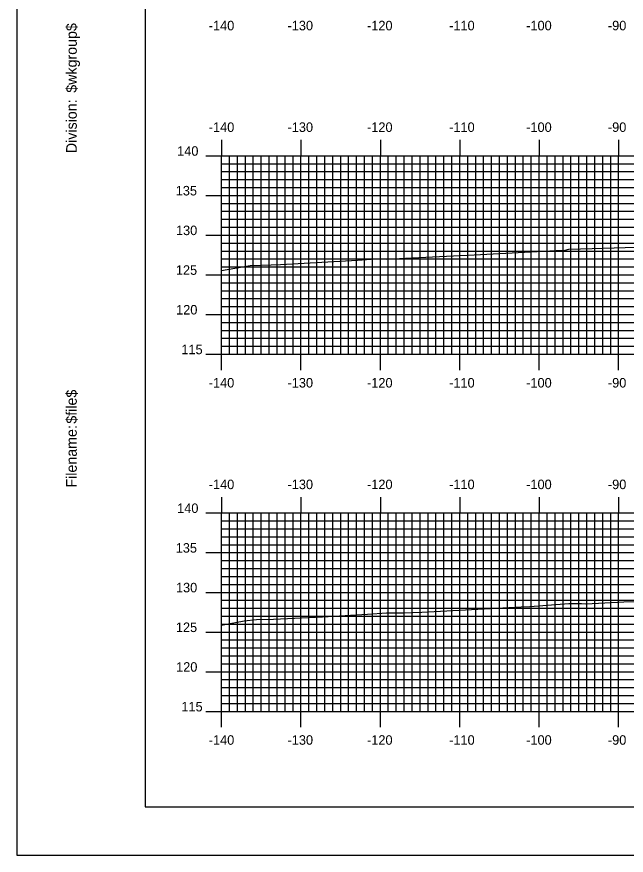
# Model space of a CAD drawing. Extents: x 841782 to 842125, y 363538 to 363758.
# Drawn here: x 841781.6 to 841858.3, y 363537.6 to 363643.2 of the extents above; entities that cross this region are included whole.
import ezdxf

# ---------------------------------------------------------------- set-up
doc = ezdxf.new("R2010")
doc.units = 0
for name, color, linetype in [('BORDER', 7, 'Continuous'), ('H_V ANNOTATION', 7, 'Continuous'), ('M_Roadway_Centerline', 7, 'Continuous'), ('MAJOR', 7, 'Continuous'), ('MINOR', 7, 'Continuous'), ('PLOT BOUNDARY', 7, 'Continuous'), ('S_Roadway_Centerline', 7, 'Continuous')]:
    doc.layers.add(name, color=color, linetype=linetype)

msp = doc.modelspace()

# ---------------------------------------------------------------- linework, layer by layer
at = {"layer": 'BORDER'}
msp.add_lwpolyline([(841797.77, 363543.72), (842117.77, 363543.72), (842117.77, 363753.72), (841797.77, 363753.72)], close=True, dxfattribs=at)
at = {"layer": 'MAJOR'}
for p, q in [((841807.37, 363627.73), (841807.37, 363625.72)), ((841817.37, 363627.73), (841817.37, 363625.72)), ((841827.37, 363627.73), (841827.37, 363625.72)), ((841837.37, 363627.73), (841837.37, 363625.72)), ((841847.37, 363627.73), (841847.37, 363625.72)), ((841857.37, 363627.73), (841857.37, 363625.72)), ((841805.37, 363625.72), (841807.37, 363625.72)), ((841807.37, 363625.72), (842087.37, 363625.72)), ((841807.37, 363600.72), (841807.37, 363625.72)), ((841807.37, 363600.72), (841807.37, 363625.72)), ((841807.37, 363625.72), (842087.37, 363625.72)), ((841817.37, 363600.72), (841817.37, 363625.72)), ((841827.37, 363600.72), (841827.37, 363625.72)), ((841837.37, 363600.72), (841837.37, 363625.72)), ((841847.37, 363600.72), (841847.37, 363625.72)), ((841857.37, 363600.72), (841857.37, 363625.72)), ((841805.37, 363620.72), (841807.37, 363620.72)), ((841807.37, 363620.72), (842087.37, 363620.72)), ((841805.37, 363615.72), (841807.37, 363615.72)), ((841807.37, 363615.72), (842087.37, 363615.72)), ((841805.37, 363610.72), (841807.37, 363610.72)), ((841807.37, 363610.72), (842087.37, 363610.72)), ((841805.37, 363605.72), (841807.37, 363605.72)), ((841807.37, 363605.72), (842087.37, 363605.72)), ((841805.37, 363600.72), (841807.37, 363600.72)), ((841807.37, 363600.72), (842087.37, 363600.72)), ((841807.37, 363600.72), (842087.37, 363600.72)), ((841807.37, 363598.72), (841807.37, 363600.72)), ((841817.37, 363598.72), (841817.37, 363600.72)), ((841827.37, 363598.72), (841827.37, 363600.72)), ((841837.37, 363598.72), (841837.37, 363600.72)), ((841847.37, 363598.72), (841847.37, 363600.72)), ((841857.37, 363598.72), (841857.37, 363600.72)), ((841807.37, 363582.73), (841807.37, 363580.72)), ((841817.37, 363582.73), (841817.37, 363580.72)), ((841827.37, 363582.73), (841827.37, 363580.72)), ((841837.37, 363582.73), (841837.37, 363580.72)), ((841847.37, 363582.73), (841847.37, 363580.72)), ((841857.37, 363582.73), (841857.37, 363580.72)), ((841805.37, 363580.72), (841807.37, 363580.72)), ((841807.37, 363580.72), (842087.37, 363580.72)), ((841807.37, 363555.72), (841807.37, 363580.72)), ((841807.37, 363555.72), (841807.37, 363580.72)), ((841807.37, 363580.72), (842087.37, 363580.72)), ((841817.37, 363555.72), (841817.37, 363580.72)), ((841827.37, 363555.72), (841827.37, 363580.72)), ((841837.37, 363555.72), (841837.37, 363580.72)), ((841847.37, 363555.72), (841847.37, 363580.72)), ((841857.37, 363555.72), (841857.37, 363580.72)), ((841805.37, 363575.72), (841807.37, 363575.72)), ((841807.37, 363575.72), (842087.37, 363575.72)), ((841805.37, 363570.72), (841807.37, 363570.72)), ((841807.37, 363570.72), (842087.37, 363570.72)), ((841805.37, 363565.72), (841807.37, 363565.72)), ((841807.37, 363565.72), (842087.37, 363565.72)), ((841805.37, 363560.72), (841807.37, 363560.72)), ((841807.37, 363560.72), (842087.37, 363560.72)), ((841805.37, 363555.72), (841807.37, 363555.72)), ((841807.37, 363555.72), (842087.37, 363555.72)), ((841807.37, 363555.72), (842087.37, 363555.72)), ((841807.37, 363553.72), (841807.37, 363555.72)), ((841817.37, 363553.72), (841817.37, 363555.72)), ((841827.37, 363553.72), (841827.37, 363555.72)), ((841837.37, 363553.72), (841837.37, 363555.72)), ((841847.37, 363553.72), (841847.37, 363555.72)), ((841857.37, 363553.72), (841857.37, 363555.72))]:
    msp.add_line(p, q, dxfattribs=at)
at = {"layer": 'MINOR'}
for p, q in [((841808.37, 363600.72), (841808.37, 363625.72)), ((841809.37, 363600.72), (841809.37, 363625.72)), ((841810.37, 363600.72), (841810.37, 363625.72)), ((841811.37, 363600.72), (841811.37, 363625.72)), ((841812.37, 363600.72), (841812.37, 363625.72)), ((841813.37, 363600.72), (841813.37, 363625.72)), ((841814.37, 363600.72), (841814.37, 363625.72)), ((841815.37, 363600.72), (841815.37, 363625.72)), ((841816.37, 363600.72), (841816.37, 363625.72)), ((841818.37, 363600.72), (841818.37, 363625.72)), ((841819.37, 363600.72), (841819.37, 363625.72)), ((841820.37, 363600.72), (841820.37, 363625.72)), ((841821.37, 363600.72), (841821.37, 363625.72)), ((841822.37, 363600.72), (841822.37, 363625.72)), ((841823.37, 363600.72), (841823.37, 363625.72)), ((841824.37, 363600.72), (841824.37, 363625.72)), ((841825.37, 363600.72), (841825.37, 363625.72)), ((841826.37, 363600.72), (841826.37, 363625.72)), ((841828.37, 363600.72), (841828.37, 363625.72)), ((841829.37, 363600.72), (841829.37, 363625.72)), ((841830.37, 363600.72), (841830.37, 363625.72)), ((841831.37, 363600.72), (841831.37, 363625.72)), ((841832.37, 363600.72), (841832.37, 363625.72)), ((841833.37, 363600.72), (841833.37, 363625.72)), ((841834.37, 363600.72), (841834.37, 363625.72)), ((841835.37, 363600.72), (841835.37, 363625.72)), ((841836.37, 363600.72), (841836.37, 363625.72)), ((841838.37, 363600.72), (841838.37, 363625.72)), ((841839.37, 363600.72), (841839.37, 363625.72)), ((841840.37, 363600.72), (841840.37, 363625.72)), ((841841.37, 363600.72), (841841.37, 363625.72)), ((841842.37, 363600.72), (841842.37, 363625.72)), ((841843.37, 363600.72), (841843.37, 363625.72)), ((841844.37, 363600.72), (841844.37, 363625.72)), ((841845.37, 363600.72), (841845.37, 363625.72)), ((841846.37, 363600.72), (841846.37, 363625.72)), ((841848.37, 363600.72), (841848.37, 363625.72)), ((841849.37, 363600.72), (841849.37, 363625.72)), ((841850.37, 363600.72), (841850.37, 363625.72)), ((841851.37, 363600.72), (841851.37, 363625.72)), ((841852.37, 363600.72), (841852.37, 363625.72)), ((841853.37, 363600.72), (841853.37, 363625.72)), ((841854.37, 363600.72), (841854.37, 363625.72)), ((841855.37, 363600.72), (841855.37, 363625.72)), ((841856.37, 363600.72), (841856.37, 363625.72)), ((841807.37, 363624.72), (842087.37, 363624.72)), ((841807.37, 363624.72), (841809.38, 363624.72)), ((841807.37, 363623.72), (842087.37, 363623.72)), ((841807.37, 363623.72), (841809.38, 363623.72)), ((841807.37, 363622.72), (842087.37, 363622.72)), ((841807.37, 363622.72), (841809.38, 363622.72)), ((841807.37, 363621.72), (842087.37, 363621.72)), ((841807.37, 363621.72), (841809.38, 363621.72)), ((841807.37, 363619.72), (842087.37, 363619.72)), ((841807.37, 363619.72), (841809.38, 363619.72)), ((841807.37, 363618.72), (842087.37, 363618.72)), ((841807.37, 363618.72), (841809.38, 363618.72)), ((841807.37, 363617.72), (842087.37, 363617.72)), ((841807.37, 363617.72), (841809.38, 363617.72)), ((841807.37, 363616.72), (842087.37, 363616.72)), ((841807.37, 363616.72), (841809.38, 363616.72)), ((841807.37, 363614.72), (842087.37, 363614.72)), ((841807.37, 363614.72), (841809.38, 363614.72)), ((841807.37, 363613.72), (842087.37, 363613.72)), ((841807.37, 363613.72), (841809.38, 363613.72)), ((841807.37, 363612.72), (842087.37, 363612.72)), ((841807.37, 363612.72), (841809.38, 363612.72)), ((841807.37, 363611.72), (842087.37, 363611.72)), ((841807.37, 363611.72), (841809.38, 363611.72)), ((841807.37, 363609.72), (842087.37, 363609.72)), ((841807.37, 363609.72), (841809.38, 363609.72)), ((841807.37, 363608.72), (842087.37, 363608.72)), ((841807.37, 363608.72), (841809.38, 363608.72)), ((841807.37, 363607.72), (842087.37, 363607.72)), ((841807.37, 363607.72), (841809.38, 363607.72)), ((841807.37, 363606.72), (842087.37, 363606.72)), ((841807.37, 363606.72), (841809.38, 363606.72)), ((841807.37, 363604.72), (842087.37, 363604.72)), ((841807.37, 363604.72), (841809.38, 363604.72)), ((841807.37, 363603.72), (842087.37, 363603.72)), ((841807.37, 363603.72), (841809.38, 363603.72)), ((841807.37, 363602.72), (842087.37, 363602.72)), ((841807.37, 363602.72), (841809.38, 363602.72)), ((841807.37, 363601.72), (842087.37, 363601.72)), ((841807.37, 363601.72), (841809.38, 363601.72)), ((841808.37, 363555.72), (841808.37, 363580.72)), ((841809.37, 363555.72), (841809.37, 363580.72)), ((841810.37, 363555.72), (841810.37, 363580.72)), ((841811.37, 363555.72), (841811.37, 363580.72)), ((841812.37, 363555.72), (841812.37, 363580.72)), ((841813.37, 363555.72), (841813.37, 363580.72)), ((841814.37, 363555.72), (841814.37, 363580.72)), ((841815.37, 363555.72), (841815.37, 363580.72)), ((841816.37, 363555.72), (841816.37, 363580.72)), ((841818.37, 363555.72), (841818.37, 363580.72)), ((841819.37, 363555.72), (841819.37, 363580.72)), ((841820.37, 363555.72), (841820.37, 363580.72)), ((841821.37, 363555.72), (841821.37, 363580.72)), ((841822.37, 363555.72), (841822.37, 363580.72)), ((841823.37, 363555.72), (841823.37, 363580.72)), ((841824.37, 363555.72), (841824.37, 363580.72)), ((841825.37, 363555.72), (841825.37, 363580.72)), ((841826.37, 363555.72), (841826.37, 363580.72)), ((841828.37, 363555.72), (841828.37, 363580.72)), ((841829.37, 363555.72), (841829.37, 363580.72)), ((841830.37, 363555.72), (841830.37, 363580.72)), ((841831.37, 363555.72), (841831.37, 363580.72)), ((841832.37, 363555.72), (841832.37, 363580.72)), ((841833.37, 363555.72), (841833.37, 363580.72)), ((841834.37, 363555.72), (841834.37, 363580.72)), ((841835.37, 363555.72), (841835.37, 363580.72)), ((841836.37, 363555.72), (841836.37, 363580.72)), ((841838.37, 363555.72), (841838.37, 363580.72)), ((841839.37, 363555.72), (841839.37, 363580.72)), ((841840.37, 363555.72), (841840.37, 363580.72)), ((841841.37, 363555.72), (841841.37, 363580.72)), ((841842.37, 363555.72), (841842.37, 363580.72)), ((841843.37, 363555.72), (841843.37, 363580.72)), ((841844.37, 363555.72), (841844.37, 363580.72)), ((841845.37, 363555.72), (841845.37, 363580.72)), ((841846.37, 363555.72), (841846.37, 363580.72)), ((841848.37, 363555.72), (841848.37, 363580.72)), ((841849.37, 363555.72), (841849.37, 363580.72)), ((841850.37, 363555.72), (841850.37, 363580.72)), ((841851.37, 363555.72), (841851.37, 363580.72)), ((841852.37, 363555.72), (841852.37, 363580.72)), ((841853.37, 363555.72), (841853.37, 363580.72)), ((841854.37, 363555.72), (841854.37, 363580.72)), ((841855.37, 363555.72), (841855.37, 363580.72)), ((841856.37, 363555.72), (841856.37, 363580.72)), ((841807.37, 363579.72), (842087.37, 363579.72)), ((841807.37, 363579.72), (841809.38, 363579.72)), ((841807.37, 363578.72), (842087.37, 363578.72)), ((841807.37, 363578.72), (841809.38, 363578.72)), ((841807.37, 363577.72), (842087.37, 363577.72)), ((841807.37, 363577.72), (841809.38, 363577.72)), ((841807.37, 363576.72), (842087.37, 363576.72)), ((841807.37, 363576.72), (841809.38, 363576.72)), ((841807.37, 363574.72), (842087.37, 363574.72)), ((841807.37, 363574.72), (841809.38, 363574.72)), ((841807.37, 363573.72), (842087.37, 363573.72)), ((841807.37, 363573.72), (841809.38, 363573.72)), ((841807.37, 363572.72), (842087.37, 363572.72)), ((841807.37, 363572.72), (841809.38, 363572.72)), ((841807.37, 363571.72), (842087.37, 363571.72)), ((841807.37, 363571.72), (841809.38, 363571.72)), ((841807.37, 363569.72), (842087.37, 363569.72)), ((841807.37, 363569.72), (841809.38, 363569.72)), ((841807.37, 363568.72), (842087.37, 363568.72)), ((841807.37, 363568.72), (841809.38, 363568.72)), ((841807.37, 363567.72), (842087.37, 363567.72)), ((841807.37, 363567.72), (841809.38, 363567.72)), ((841807.37, 363566.72), (842087.37, 363566.72)), ((841807.37, 363566.72), (841809.38, 363566.72)), ((841807.37, 363564.72), (842087.37, 363564.72)), ((841807.37, 363564.72), (841809.38, 363564.72)), ((841807.37, 363563.72), (842087.37, 363563.72)), ((841807.37, 363563.72), (841809.38, 363563.72)), ((841807.37, 363562.72), (842087.37, 363562.72)), ((841807.37, 363562.72), (841809.38, 363562.72)), ((841807.37, 363561.72), (842087.37, 363561.72)), ((841807.37, 363561.72), (841809.38, 363561.72)), ((841807.37, 363559.72), (842087.37, 363559.72)), ((841807.37, 363559.72), (841809.38, 363559.72)), ((841807.37, 363558.72), (842087.37, 363558.72)), ((841807.37, 363558.72), (841809.38, 363558.72)), ((841807.37, 363557.72), (842087.37, 363557.72)), ((841807.37, 363557.72), (841809.38, 363557.72)), ((841807.37, 363556.72), (842087.37, 363556.72)), ((841807.37, 363556.72), (841809.38, 363556.72))]:
    msp.add_line(p, q, dxfattribs=at)
at = {"layer": 'PLOT BOUNDARY'}
msp.add_lwpolyline([(841781.59, 363537.6), (842121.59, 363537.6), (842121.59, 363757.6), (841781.59, 363757.6)], close=True, dxfattribs=at)
at = {"layer": 'S_Roadway_Centerline'}
for points in [[(841807.37, 363611.28), (841810.99, 363611.91), (841813.6, 363611.97), (841814.81, 363612.04), (841824.5, 363612.56), (841826.8, 363612.74), (841828.17, 363612.71), (841831.35, 363612.86), (841839.17, 363613.25), (841849.5, 363613.77), (841850.64, 363613.84), (841851.11, 363613.94), (841854.04, 363614.05), (841863.74, 363614.32)], [(841807.37, 363566.57), (841810.23, 363567.15), (841811.76, 363567.31), (841813.9, 363567.35), (841820.08, 363567.63), (841825.74, 363567.97), (841828.14, 363568.15), (841830.32, 363568.14), (841832.59, 363568.24), (841841.99, 363568.72), (841845.1, 363568.88), (841846.2, 363568.94), (841851.12, 363569.31), (841852.71, 363569.33), (841853.25, 363569.29), (841858.01, 363569.53), (841866.24, 363569.69)]]:
    msp.add_lwpolyline(points, dxfattribs=at)

# ---------------------------------------------------------------- texts
at = {"layer": 'BORDER'}
for s, p in [('$wkgroup$', (841789.14, 363633.66)), ('Division:', (841789.14, 363626.05)), ('$file$', (841789.14, 363591.97)), ('Filename:', (841789.14, 363583.92))]:
    msp.add_text(s, height=1.339, rotation=90, dxfattribs=at).set_placement(p)
at = {"layer": 'H_V ANNOTATION'}
for s, p in [('-140', (841805.76, 363641.52)), ('-130', (841815.68, 363641.52)), ('-120', (841825.69, 363641.52)), ('-110', (841836.03, 363641.52)), ('-100', (841845.73, 363641.52)), ('-90', (841856.02, 363641.52)), ('-140', (841805.76, 363628.72)), ('-130', (841815.68, 363628.72)), ('-120', (841825.69, 363628.72)), ('-110', (841836.03, 363628.72)), ('-100', (841845.73, 363628.72)), ('-90', (841856.02, 363628.72)), ('140', (841801.78, 363625.72)), ('135', (841801.6, 363620.72)), ('130', (841801.63, 363615.72)), ('125', (841801.62, 363610.72)), ('120', (841801.65, 363605.72)), ('115', (841802.31, 363600.72)), ('-140', (841805.76, 363596.52)), ('-130', (841815.68, 363596.52)), ('-120', (841825.69, 363596.52)), ('-110', (841836.03, 363596.52)), ('-100', (841845.73, 363596.52)), ('-90', (841856.02, 363596.52)), ('-140', (841805.76, 363583.72)), ('-130', (841815.68, 363583.72)), ('-120', (841825.69, 363583.72)), ('-110', (841836.03, 363583.72)), ('-100', (841845.73, 363583.72)), ('-90', (841856.02, 363583.72)), ('140', (841801.78, 363580.72)), ('135', (841801.6, 363575.72)), ('130', (841801.63, 363570.72)), ('125', (841801.62, 363565.72)), ('120', (841801.65, 363560.72)), ('115', (841802.31, 363555.72)), ('-140', (841805.76, 363551.52)), ('-130', (841815.68, 363551.52)), ('-120', (841825.69, 363551.52)), ('-110', (841836.03, 363551.52)), ('-100', (841845.73, 363551.52)), ('-90', (841856.02, 363551.52))]:
    msp.add_text(s, height=1.2, dxfattribs=at).set_placement(p)
at = {"layer": 'M_Roadway_Centerline'}
for s, p in [('C', (841851.1, 363613.94)), ('L', (841851.11, 363613.94)), ('C', (841826.8, 363612.74)), ('L', (841826.8, 363612.74)), ('C', (841851.12, 363569.31)), ('L', (841851.12, 363569.31)), ('C', (841828.13, 363568.15)), ('L', (841828.14, 363568.15))]:
    msp.add_text(s, height=0.0146, dxfattribs=at).set_placement(p)
at = {"layer": 'MAJOR'}
for p in [(841807.36, 363600.72), (841807.36, 363555.72)]:
    msp.add_text('-', height=0.012, dxfattribs=at).set_placement(p)

doc.saveas('drawing.dxf')
